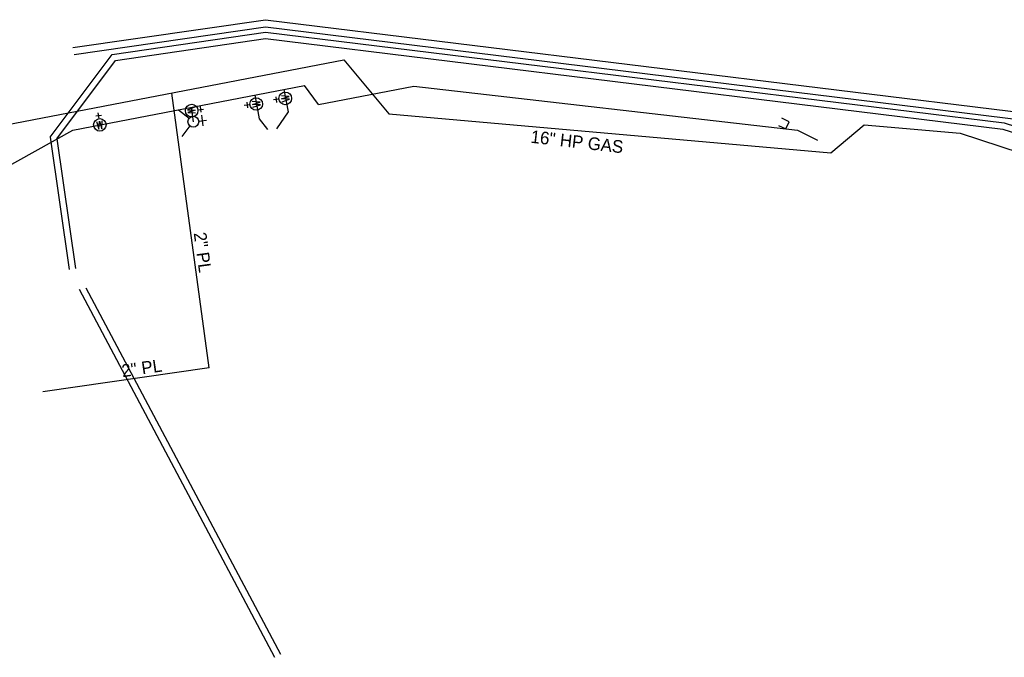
# Model space of a CAD drawing. Extents: x 1825330 to 1832613, y 710925 to 712586.
# Drawn here: x 1827651.9 to 1827870.9, y 711537.1 to 711678.9 of the extents above; entities that cross this region are included whole.
import ezdxf

# ---------------------------------------------------------------- set-up
doc = ezdxf.new("R2010")
doc.units = 0
for name, color, linetype in [('COC_BLD', 7, 'Continuous'), ('COC_MCS_BENCH', 7, 'Continuous'), ('COC_UELC_GUY', 7, 'Continuous'), ('COC_USAN_MH', 7, 'Continuous'), ('COC_USAN_MH_TEXT', 7, 'Continuous'), ('COC_UWAT_HYD', 7, 'Continuous'), ('P-TEXT', 7, 'Continuous')]:
    doc.layers.add(name, color=color, linetype=linetype)

msp = doc.modelspace()

# ---------------------------------------------------------------- linework, layer by layer
at = {"layer": 'COC_MCS_BENCH'}
msp.add_lwpolyline([(1827723.98, 711669.92), (1827734, 711657.95), (1827832.29, 711649.24), (1827839.75, 711655.48), (1827861.07, 711653.59)], dxfattribs=at)
at = {"layer": 'COC_UELC_GUY'}
for p, q in [((1827663.71, 711654.32), (1827715.2, 711664.23)), ((1827718.33, 711660.02), (1827715.2, 711664.23)), ((1827718.33, 711660.02), (1827739.56, 711664.1)), ((1827739.56, 711664.1), (1827824.88, 711654.28)), ((1827710.62, 711663.35), (1827711.6, 711658.36)), ((1827690.51, 711656.17), (1827690.09, 711659.39)), ((1827705.16, 711656.78), (1827707.02, 711654.43)), ((1827643.6, 711643.1), (1827663.71, 711654.32)), ((1827824.88, 711654.28), (1827829.37, 711652.08))]:
    msp.add_line(p, q, dxfattribs=at)
for points in [[(1827704.16, 711662.1), (1827705.16, 711656.78), (1827707.02, 711654.43)], [(1827710.62, 711663.35), (1827711.6, 711658.36), (1827709.02, 711654.59)]]:
    msp.add_lwpolyline(points, dxfattribs=at)
at = {"layer": 'COC_USAN_MH'}
for p, q in [((1827612.04, 711648.37), (1827723.98, 711669.92)), ((1827685.63, 711662.54), (1827693.97, 711601.43)), ((1827694, 711601.43), (1827657.03, 711596.08))]:
    msp.add_line(p, q, dxfattribs=at)
msp.add_lwpolyline([(1827861.07, 711653.59), (1827932.11, 711630.33), (1827978.94, 711622.09), (1828023.5, 711618.65)], dxfattribs=at)
at = {"layer": 'COC_USAN_MH_TEXT'}
for p, q in [((1827672.44, 711671.13), (1827706.55, 711676.08)), ((1827706.55, 711676.08), (1827870.9, 711655.89)), ((1827673.22, 711669.81), (1827706.56, 711674.65)), ((1827706.56, 711674.65), (1827870.6, 711654.5)), ((1827658.68, 711652.71), (1827672.44, 711671.13)), ((1827660.17, 711652.33), (1827673.22, 711669.81)), ((1827870.9, 711655.89), (1827913.78, 711642.33)), ((1827870.6, 711654.5), (1827913.48, 711640.94)), ((1827658.68, 711652.71), (1827662.9, 711623.32)), ((1827660.17, 711652.33), (1827664.31, 711623.52)), ((1827665.08, 711618.93), (1827708.59, 711537.08)), ((1827666.61, 711619.26), (1827709.91, 711537.78))]:
    msp.add_line(p, q, dxfattribs=at)
at = {"layer": 'COC_UWAT_HYD'}
for p, q in [((1827663.72, 711672.64), (1827706.52, 711678.86)), ((1827663.97, 711671.08), (1827706.54, 711677.26)), ((1827706.52, 711678.86), (1827877.6, 711657.83)), ((1827706.54, 711677.26), (1827877.26, 711656.28))]:
    msp.add_line(p, q, dxfattribs=at)
at = {"layer": 'P-TEXT'}
for p, q in [((1827703.1, 711659.94), (1827701.84, 711659.78)), ((1827702.39, 711660.49), (1827702.55, 711659.23)), ((1827709.56, 711661.18), (1827708.3, 711661.03)), ((1827708.85, 711661.74), (1827709.01, 711660.47)), ((1827670.08, 711657.57), (1827668.82, 711657.41)), ((1827669.53, 711656.86), (1827669.37, 711658.12)), ((1827689.56, 711656.91), (1827687.24, 711658.72)), ((1827691.53, 711658.82), (1827692.79, 711658.97)), ((1827692.24, 711658.26), (1827692.08, 711659.53)), ((1827692.7, 711655.23), (1827692.41, 711657.61)), ((1827691.7, 711656.32), (1827693.4, 711656.52)), ((1827689.76, 711655.23), (1827687.95, 711652.91))]:
    msp.add_line(p, q, dxfattribs=at)
for points in [[(1827703.77, 711659.38), (1827705.44, 711659.91), (1827703.69, 711660.01), (1827705.36, 711660.54), (1827703.62, 711660.65)], [(1827710.23, 711660.62), (1827711.9, 711661.15), (1827710.15, 711661.26), (1827711.82, 711661.79), (1827710.08, 711661.89)], [(1827690.86, 711659.37), (1827689.19, 711658.84), (1827690.94, 711658.74), (1827689.27, 711658.21), (1827691.02, 711658.11)], [(1827668.97, 711656.19), (1827669.5, 711654.52), (1827669.6, 711656.27), (1827670.13, 711654.6), (1827670.24, 711656.35)], [(1827820.67, 711655.32), (1827822.28, 711654.56), (1827823.05, 711656.18), (1827821.43, 711656.94)]]:
    msp.add_lwpolyline(points, dxfattribs=at)
for centre, radius in [((1827710.95, 711661.36), 1.4), ((1827690.14, 711658.64), 1.4), ((1827704.49, 711660.11), 1.4), ((1827669.7, 711655.47), 1.4), ((1827690.51, 711656.17), 1.2)]:
    msp.add_circle(centre, radius, dxfattribs=at)

# ---------------------------------------------------------------- texts
at = {"layer": 'COC_BLD'}
msp.add_text('16" HP GAS', height=2.8, rotation=353.4359, dxfattribs=at).set_placement((1827765.43, 711651.51))
at = {"layer": 'COC_MCS_BENCH'}
for rotation, p in [(277.7651, (1827690.58, 711631.41)), (8.2423, (1827674.76, 711599.35))]:
    msp.add_text('2" PL', height=2.8, rotation=rotation, dxfattribs=at).set_placement(p)

doc.saveas('drawing.dxf')
